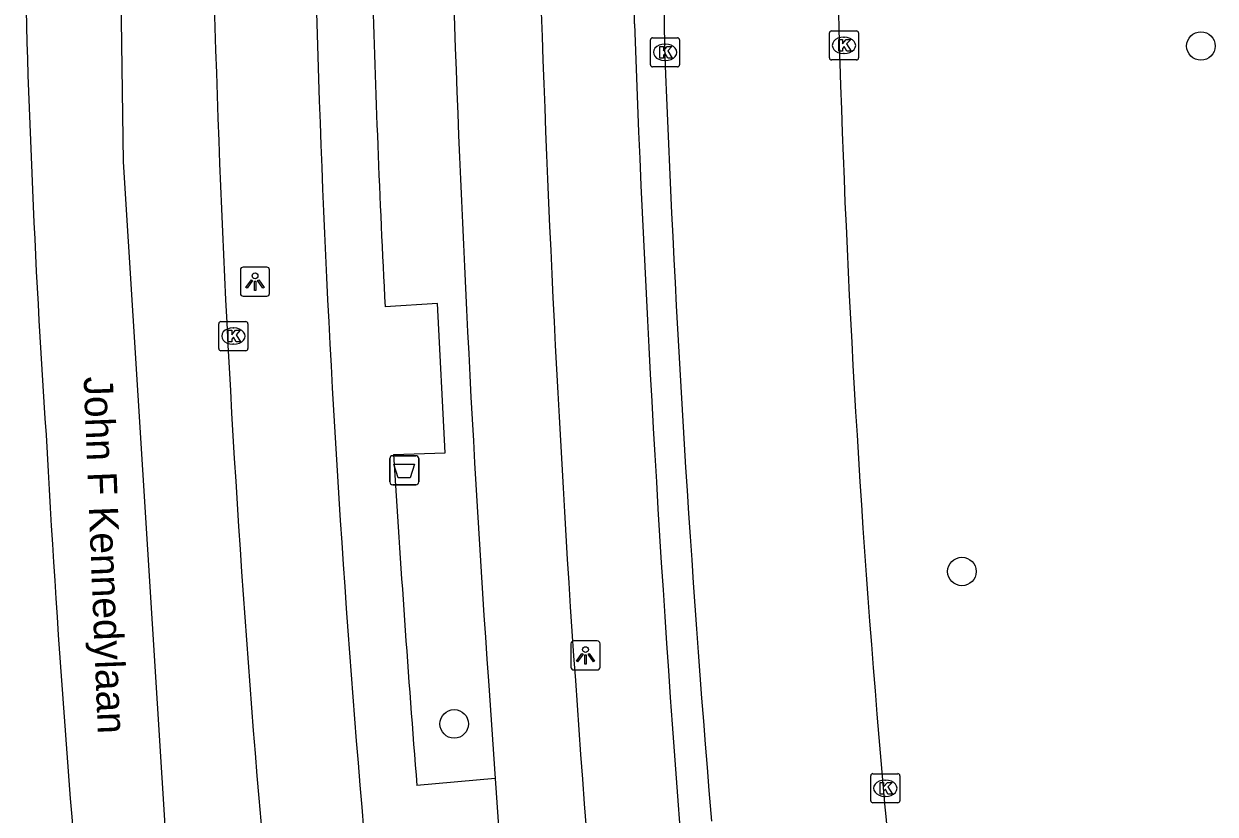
# Model space of a CAD drawing. Extents: x 161477 to 163040, y 383680 to 384868.
# Drawn here: x 161509.36 to 161550.19, y 384061.82 to 384088.93 of the extents above; entities that cross this region are included whole.
import ezdxf

# ---------------------------------------------------------------- set-up
doc = ezdxf.new("R2010")
doc.units = 0
for name, color, linetype in [('IMGEO_Afvalbak', 7, 'Continuous'), ('IMGEO_Boom', 7, 'Continuous'), ('IMGEO_Fietspad_open', 7, 'Continuous'), ('IMGEO_Kolk', 7, 'Continuous'), ('IMGEO_Lichtpunt', 7, 'Continuous'), ('IMGEO_Openbare_ruimte_label', 7, 'Continuous'), ('IMGEO_OVBaan_gesloten', 7, 'Continuous'), ('IMGEO_Rijbaan_lokaal_gesloten', 7, 'Continuous'), ('IMGEO_Rijbaan_lokaal_open', 7, 'Continuous'), ('IMGEO_Voetpad_open', 7, 'Continuous')]:
    doc.layers.add(name, color=color, linetype=linetype)

msp = doc.modelspace()

# ---------------------------------------------------------------- linework, layer by layer
at = {"layer": 'IMGEO_Afvalbak'}
for p, q in [((161521.902, 384073.218), (161521.902, 384074.018)), ((161521.902, 384074.018), (161521.902, 384073.218)), ((161522.002, 384074.118), (161522.792, 384074.118)), ((161522.792, 384074.118), (161522.002, 384074.118)), ((161522.892, 384074.018), (161522.892, 384073.218)), ((161522.892, 384073.218), (161522.892, 384074.018)), ((161522.792, 384073.118), (161522.002, 384073.118)), ((161522.002, 384073.118), (161522.792, 384073.118))]:
    msp.add_line(p, q, dxfattribs=at)
msp.add_lwpolyline([(161522.045, 384073.832), (161522.749, 384073.832), (161522.6, 384073.362), (161522.194, 384073.362), (161522.045, 384073.832)], dxfattribs=at)
for centre, start, end in [((161522.002, 384074.018), 90, 180), ((161522.002, 384074.018), 90, 180), ((161522.792, 384074.018), 0, 90), ((161522.792, 384074.018), 360, 90), ((161522.002, 384073.218), 180, 270), ((161522.002, 384073.218), 180, 270), ((161522.792, 384073.218), 270, 0), ((161522.792, 384073.218), 270, 0)]:
    msp.add_arc(centre, 0.1, start, end, dxfattribs=at)
at = {"layer": 'IMGEO_Boom'}
for centre in [(161549.705, 384088.17), (161541.513, 384070.146), (161524.109, 384064.919)]:
    msp.add_circle(centre, 0.489, dxfattribs=at)
at = {"layer": 'IMGEO_Fietspad_open'}
msp.add_lwpolyline([(161525.28, 384066.396), (161525.511, 384063.044)], dxfattribs=at)
for centre, radius, start, end in [((162194.711, 384111.674), 667.99, 181.427877, 183.668064), ((162190.499, 384111.979), 666.779, 181.85899, 183.919982), ((162521.881, 384135.354), 996.008, 183.823363, 185.383124)]:
    msp.add_arc(centre, radius, start, end, dxfattribs=at)
at = {"layer": 'IMGEO_Kolk'}
for p, q in [((161530.911, 384088.455), (161531.763, 384088.455)), ((161536.97, 384087.765), (161536.97, 384088.617)), ((161537.045, 384088.691), (161537.897, 384088.691)), ((161537.458, 384088.471), (161537.483, 384088.471)), ((161537.971, 384088.617), (161537.971, 384087.765)), ((161530.836, 384087.529), (161530.836, 384088.381)), ((161531.324, 384088.235), (161531.349, 384088.235)), ((161531.837, 384088.381), (161531.837, 384087.529)), ((161531.347, 384087.675), (161531.322, 384087.675)), ((161537.897, 384087.691), (161537.045, 384087.691)), ((161537.481, 384087.911), (161537.456, 384087.911)), ((161531.763, 384087.455), (161530.911, 384087.455)), ((161516.039, 384077.794), (161516.039, 384078.646)), ((161516.114, 384078.72), (161516.966, 384078.72)), ((161517.04, 384078.646), (161517.04, 384077.794)), ((161516.527, 384078.5), (161516.552, 384078.5)), ((161516.55, 384077.94), (161516.525, 384077.94)), ((161516.966, 384077.72), (161516.114, 384077.72)), ((161538.386, 384062.285), (161538.386, 384063.137)), ((161538.461, 384063.211), (161539.313, 384063.211)), ((161539.387, 384063.137), (161539.387, 384062.285)), ((161538.874, 384062.991), (161538.899, 384062.991)), ((161538.897, 384062.431), (161538.872, 384062.431)), ((161539.313, 384062.211), (161538.461, 384062.211))]:
    msp.add_line(p, q, dxfattribs=at)
for points in [[(161530.911, 384088.455), (161531.763, 384088.455)], [(161536.97, 384087.765), (161536.97, 384088.617)], [(161537.045, 384088.691), (161537.897, 384088.691)], [(161537.971, 384088.617), (161537.971, 384087.765)], [(161530.836, 384087.529), (161530.836, 384088.381)], [(161531.157, 384088.155), (161531.28, 384088.155), (161531.28, 384088.004), (161531.41, 384088.155), (161531.574, 384088.155), (161531.428, 384088.004), (161531.581, 384087.755), (161531.429, 384087.755), (161531.344, 384087.919), (161531.28, 384087.852), (161531.28, 384087.755), (161531.157, 384087.755), (161531.157, 384088.155)], [(161531.837, 384088.381), (161531.837, 384087.529)], [(161537.291, 384088.391), (161537.414, 384088.391), (161537.414, 384088.24), (161537.544, 384088.391), (161537.708, 384088.391), (161537.562, 384088.24), (161537.715, 384087.991), (161537.563, 384087.991), (161537.478, 384088.155), (161537.414, 384088.088), (161537.414, 384087.991), (161537.291, 384087.991), (161537.291, 384088.391)], [(161537.897, 384087.691), (161537.045, 384087.691)], [(161531.763, 384087.455), (161530.911, 384087.455)], [(161516.039, 384077.794), (161516.039, 384078.646)], [(161516.114, 384078.72), (161516.966, 384078.72)], [(161517.04, 384078.646), (161517.04, 384077.794)], [(161516.36, 384078.42), (161516.483, 384078.42), (161516.483, 384078.269), (161516.613, 384078.42), (161516.777, 384078.42), (161516.631, 384078.269), (161516.784, 384078.02), (161516.632, 384078.02), (161516.547, 384078.184), (161516.483, 384078.117), (161516.483, 384078.02), (161516.36, 384078.02), (161516.36, 384078.42)], [(161516.966, 384077.72), (161516.114, 384077.72)], [(161538.386, 384062.285), (161538.386, 384063.137)], [(161538.461, 384063.211), (161539.313, 384063.211)], [(161539.387, 384063.137), (161539.387, 384062.285)], [(161538.707, 384062.911), (161538.83, 384062.911), (161538.83, 384062.76), (161538.96, 384062.911), (161539.124, 384062.911), (161538.978, 384062.76), (161539.131, 384062.511), (161538.979, 384062.511), (161538.894, 384062.675), (161538.83, 384062.608), (161538.83, 384062.511), (161538.707, 384062.511), (161538.707, 384062.911)], [(161539.313, 384062.211), (161538.461, 384062.211)]]:
    msp.add_lwpolyline(points, dxfattribs=at)
for centre, start, end in [((161530.913, 384088.379), 91.552, 178.448), ((161530.913, 384088.379), 91.552, 178.448), ((161531.761, 384088.379), 1.552, 88.448), ((161531.761, 384088.379), 1.552, 88.448), ((161537.047, 384088.615), 91.552, 178.448), ((161537.047, 384088.615), 91.552, 178.448), ((161537.895, 384088.615), 1.552, 88.448), ((161537.895, 384088.615), 1.552, 88.448), ((161537.047, 384087.767), 181.552, 268.448), ((161537.047, 384087.767), 181.552, 268.448), ((161537.895, 384087.767), 271.552, 358.448), ((161537.895, 384087.767), 271.552, 358.448), ((161530.913, 384087.531), 181.552, 268.448), ((161530.913, 384087.531), 181.552, 268.448), ((161531.761, 384087.531), 271.552, 358.448), ((161531.761, 384087.531), 271.552, 358.448), ((161516.116, 384078.644), 91.552, 178.448), ((161516.116, 384078.644), 91.552, 178.448), ((161516.964, 384078.644), 1.552, 88.448), ((161516.964, 384078.644), 1.552, 88.448), ((161516.116, 384077.796), 181.552, 268.448), ((161516.116, 384077.796), 181.552, 268.448), ((161516.964, 384077.796), 271.552, 358.448), ((161516.964, 384077.796), 271.552, 358.448), ((161538.463, 384063.135), 91.552, 178.448), ((161538.463, 384063.135), 91.552, 178.448), ((161539.311, 384063.135), 1.552, 88.448), ((161539.311, 384063.135), 1.552, 88.448), ((161538.463, 384062.287), 181.552, 268.448), ((161538.463, 384062.287), 181.552, 268.448), ((161539.311, 384062.287), 271.552, 358.448), ((161539.311, 384062.287), 271.552, 358.448)]:
    msp.add_arc(centre, 0.0765, start, end, dxfattribs=at)
for centre, major_axis, ratio, start_param, end_param in [((161537.457, 384088.191), (-0.387, 0.002), 0.722429, 4.712389, 7.853982), ((161537.482, 384088.191), (-0.39, 0.002), 0.717154, 1.570796, 4.712389), ((161531.323, 384087.955), (-0.387, 0.002), 0.722429, 4.712389, 7.853982), ((161531.348, 384087.955), (-0.39, 0.002), 0.717154, 1.570796, 4.712389), ((161516.526, 384078.22), (-0.387, 0.002), 0.722429, 4.712389, 7.853982), ((161516.551, 384078.22), (-0.39, 0.002), 0.717154, 1.570796, 4.712389), ((161538.873, 384062.711), (-0.387, 0.002), 0.722429, 4.712389, 7.853982), ((161538.898, 384062.711), (-0.39, 0.002), 0.717154, 1.570796, 4.712389)]:
    msp.add_ellipse(centre, major_axis=major_axis, ratio=ratio, start_param=start_param, end_param=end_param, dxfattribs=at)
at = {"layer": 'IMGEO_Lichtpunt'}
for p, q in [((161516.783, 384080.49), (161516.783, 384079.683)), ((161516.783, 384080.49), (161516.783, 384079.683)), ((161517.685, 384080.585), (161516.877, 384080.585)), ((161517.685, 384080.585), (161516.877, 384080.585)), ((161517.779, 384079.683), (161517.779, 384080.49)), ((161517.779, 384079.683), (161517.779, 384080.49)), ((161516.877, 384079.589), (161517.685, 384079.589)), ((161516.877, 384079.589), (161517.685, 384079.589)), ((161528.112, 384067.669), (161528.112, 384066.862)), ((161528.112, 384067.669), (161528.112, 384066.862)), ((161529.014, 384067.764), (161528.206, 384067.764)), ((161529.014, 384067.764), (161528.206, 384067.764)), ((161529.108, 384066.862), (161529.108, 384067.669)), ((161529.108, 384066.862), (161529.108, 384067.669)), ((161528.206, 384066.768), (161529.014, 384066.768)), ((161528.206, 384066.768), (161529.014, 384066.768))]:
    msp.add_line(p, q, dxfattribs=at)
for points in [[(161517.157, 384080.154), (161517.196, 384080.126), (161517.008, 384079.864), (161516.97, 384079.891), (161517.157, 384080.154)], [(161517.259, 384080.106), (161517.306, 384080.106), (161517.306, 384079.784), (161517.259, 384079.784), (161517.259, 384080.106)], [(161517.369, 384080.126), (161517.407, 384080.153), (161517.594, 384079.891), (161517.555, 384079.863), (161517.369, 384080.126)], [(161528.486, 384067.333), (161528.525, 384067.305), (161528.337, 384067.043), (161528.299, 384067.07), (161528.486, 384067.333)], [(161528.588, 384067.285), (161528.635, 384067.285), (161528.635, 384066.963), (161528.588, 384066.963), (161528.588, 384067.285)], [(161528.698, 384067.305), (161528.736, 384067.332), (161528.923, 384067.07), (161528.884, 384067.042), (161528.698, 384067.305)]]:
    msp.add_lwpolyline(points, dxfattribs=at)
for centre in [(161517.282, 384080.288), (161528.611, 384067.467)]:
    msp.add_circle(centre, 0.0994, dxfattribs=at)
for centre, start, end in [((161516.877, 384080.49), 90, 180), ((161516.877, 384080.49), 90, 180), ((161517.685, 384080.49), 0, 90), ((161517.685, 384080.49), 0, 90), ((161516.877, 384079.683), 180, 270), ((161516.877, 384079.683), 180, 270), ((161517.685, 384079.683), 270, 0), ((161517.685, 384079.683), 270, 360), ((161528.206, 384067.669), 90, 180), ((161528.206, 384067.669), 90, 180), ((161529.014, 384067.669), 0, 90), ((161529.014, 384067.669), 0, 90), ((161528.206, 384066.862), 180, 270), ((161528.206, 384066.862), 180, 270), ((161529.014, 384066.862), 270, 0), ((161529.014, 384066.862), 270, 360)]:
    msp.add_arc(centre, 0.0946, start, end, dxfattribs=at)
at = {"layer": 'IMGEO_OVBaan_gesloten'}
for centre, radius, start, end in [((162006.795, 384103.458), 491.106, 181.16373, 186.98146), ((162003.689, 384103.252), 484.502, 181.28861, 187.02918)]:
    msp.add_arc(centre, radius, start, end, dxfattribs=at)
at = {"layer": 'IMGEO_Rijbaan_lokaal_gesloten'}
for points in [[(161519.658, 384016.476), (161516.91, 384036.302), (161514.276, 384060.331), (161512.771, 384084.199), (161512.45, 384106.854)], [(161531.174, 384099.384), (161531.32, 384088.12), (161531.356, 384087.19)], [(161537.32, 384087.82), (161537.327, 384087.599)], [(161538.872, 384062.067), (161538.89, 384061.86), (161540.832, 384041.57), (161540.88, 384041.114)], [(161532.907, 384061.846), (161532.926, 384061.585)]]:
    msp.add_lwpolyline(points, dxfattribs=at)
for centre, radius, start, end in [((162047.346, 384103.272), 510.26, 179.99265, 181.73528), ((161870.69, 384099.146), 361.389, 181.00836, 183.85803), ((161984.51, 384101.846), 447.41, 181.82484, 185.10092), ((162116.096, 384110.255), 585.195, 182.258894, 184.745135), ((162020.3, 384102.502), 510.93, 183.10469, 185.34779)]:
    msp.add_arc(centre, radius, start, end, dxfattribs=at)
at = {"layer": 'IMGEO_Rijbaan_lokaal_open'}
for points in [[(161522.026, 384074.158), (161523.8, 384074.218), (161523.534, 384079.342), (161521.741, 384079.227)], [(161525.511, 384063.044), (161522.828, 384062.803)], [(161525.511, 384063.044), (161525.665, 384060.913)]]:
    msp.add_lwpolyline(points, dxfattribs=at)
for centre, radius, start, end in [((161990.633, 384103.363), 469.513, 181.59445, 182.94668), ((162296.446, 384123.149), 775.968, 183.619811, 184.460335)]:
    msp.add_arc(centre, radius, start, end, dxfattribs=at)
at = {"layer": 'IMGEO_Voetpad_open'}
msp.add_lwpolyline([(161530.287, 384088.932), (161530.155, 384099.073), (161530.14, 384099.502)], dxfattribs=at)
msp.add_arc((162231.505, 384114.608), 701.688, 182.097053, 184.515444, dxfattribs=at)

# ---------------------------------------------------------------- texts
at = {"layer": 'IMGEO_Openbare_ruimte_label'}
msp.add_text('John F Kennedylaan', height=1, rotation=272.2929, dxfattribs=at).set_placement((161511.406, 384076.82))

doc.saveas('drawing.dxf')
